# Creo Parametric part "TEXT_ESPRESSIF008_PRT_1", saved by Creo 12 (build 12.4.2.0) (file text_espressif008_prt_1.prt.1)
Units: Custom; MM, KILOGRAM, SECS

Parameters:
  PTC_WM_ITERATION = "0"
  PTC_WM_VERSION = "-.0"
  PTC_WM_LIFECYCLE_STATE = "In Work"
  PTC_WM_LIFECYCLE = "MO_CADDocument"
  PTC_WM_CREATED_BY = "Maximilian Roepper (Z0017RMS: MO)"
  PTC_WM_CREATED_ON = "18-Sep-26 11:36:42 AM"
  PTC_WM_MODIFIED_BY = "Maximilian Roepper (Z0017RMS: MO)"
  PTC_WM_MODIFIED_ON = "18-Sep-26 11:36:46 AM"
  PDMLINKNUMBER = "PDM000071455006"
  PTC_WM_NAME = "text_espressif008_prt_1.prt"
  PTC_WM_NUMBER = "PDM000071455006"

Other parameters: WEIGHT, WEIGHT_FACTOR, WEIGHT_ADD, _MASS_TEMP, _DIFF_TEMP, MC_ERRORS, SUPPLIER

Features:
  1. coordinate system
  2. datum plane "PRT_YZ"
  3. datum plane "PRT_XY"
  4. datum plane "PRT_XZ"
  5. coordinate system
  6. datum axis
  7. datum axis
  8. datum axis
  9. coordinate system
  10. imported feature
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
Other named items: PRT, SIEMENS_MO, DRW_VIEW_ORG, PRT_X, PRT_Y, PRT_Z, CS0, ROUGH_GROB

Layers: 00_STD_CSYS-KSYS, 01_STD_PLANES-EBENEN, 02_STD_AXES-ACHSEN, 03_STD_CSYS-KSYS, 24_IMPORT_FEAT-IMPORT_KE

Surfaces: 12 plane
